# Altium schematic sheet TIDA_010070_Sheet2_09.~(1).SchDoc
size 431 x 279 mm; Date: Not shown in title block; ApprovedBy: Not shown in title block; CheckedBy: Not shown in title block; Author: Not shown in title block; CompanyName: Not shown in title block; Engineer: Not shown in title block; Organization: Not shown in title block; Address1: Not shown in title block; Address2: Not shown in title block; Address3: Not shown in title block; Address4: Not shown in title block; DocumentNumber: 2; Revision: Use project parameter SCH_Rev; SheetNumber: 2; SheetTotal: 3; PageSetup: Record=PageOptions¦CenterHorizontal=True¦CenterVertical=True¦PrintScale=1.00¦XCorrection=1.00¦YCorrection=1.00¦PrintKind=0¦BorderSize=5000000¦LeftOffset=0¦BottomOffset=0¦Orientation=2¦PaperLength=1000¦PaperWidth=1000¦Scale=100¦PaperSource=15¦PrintQuality=600¦MediaType=1¦DitherType=10¦PaperKind=Letter¦PrintScaleMode=1
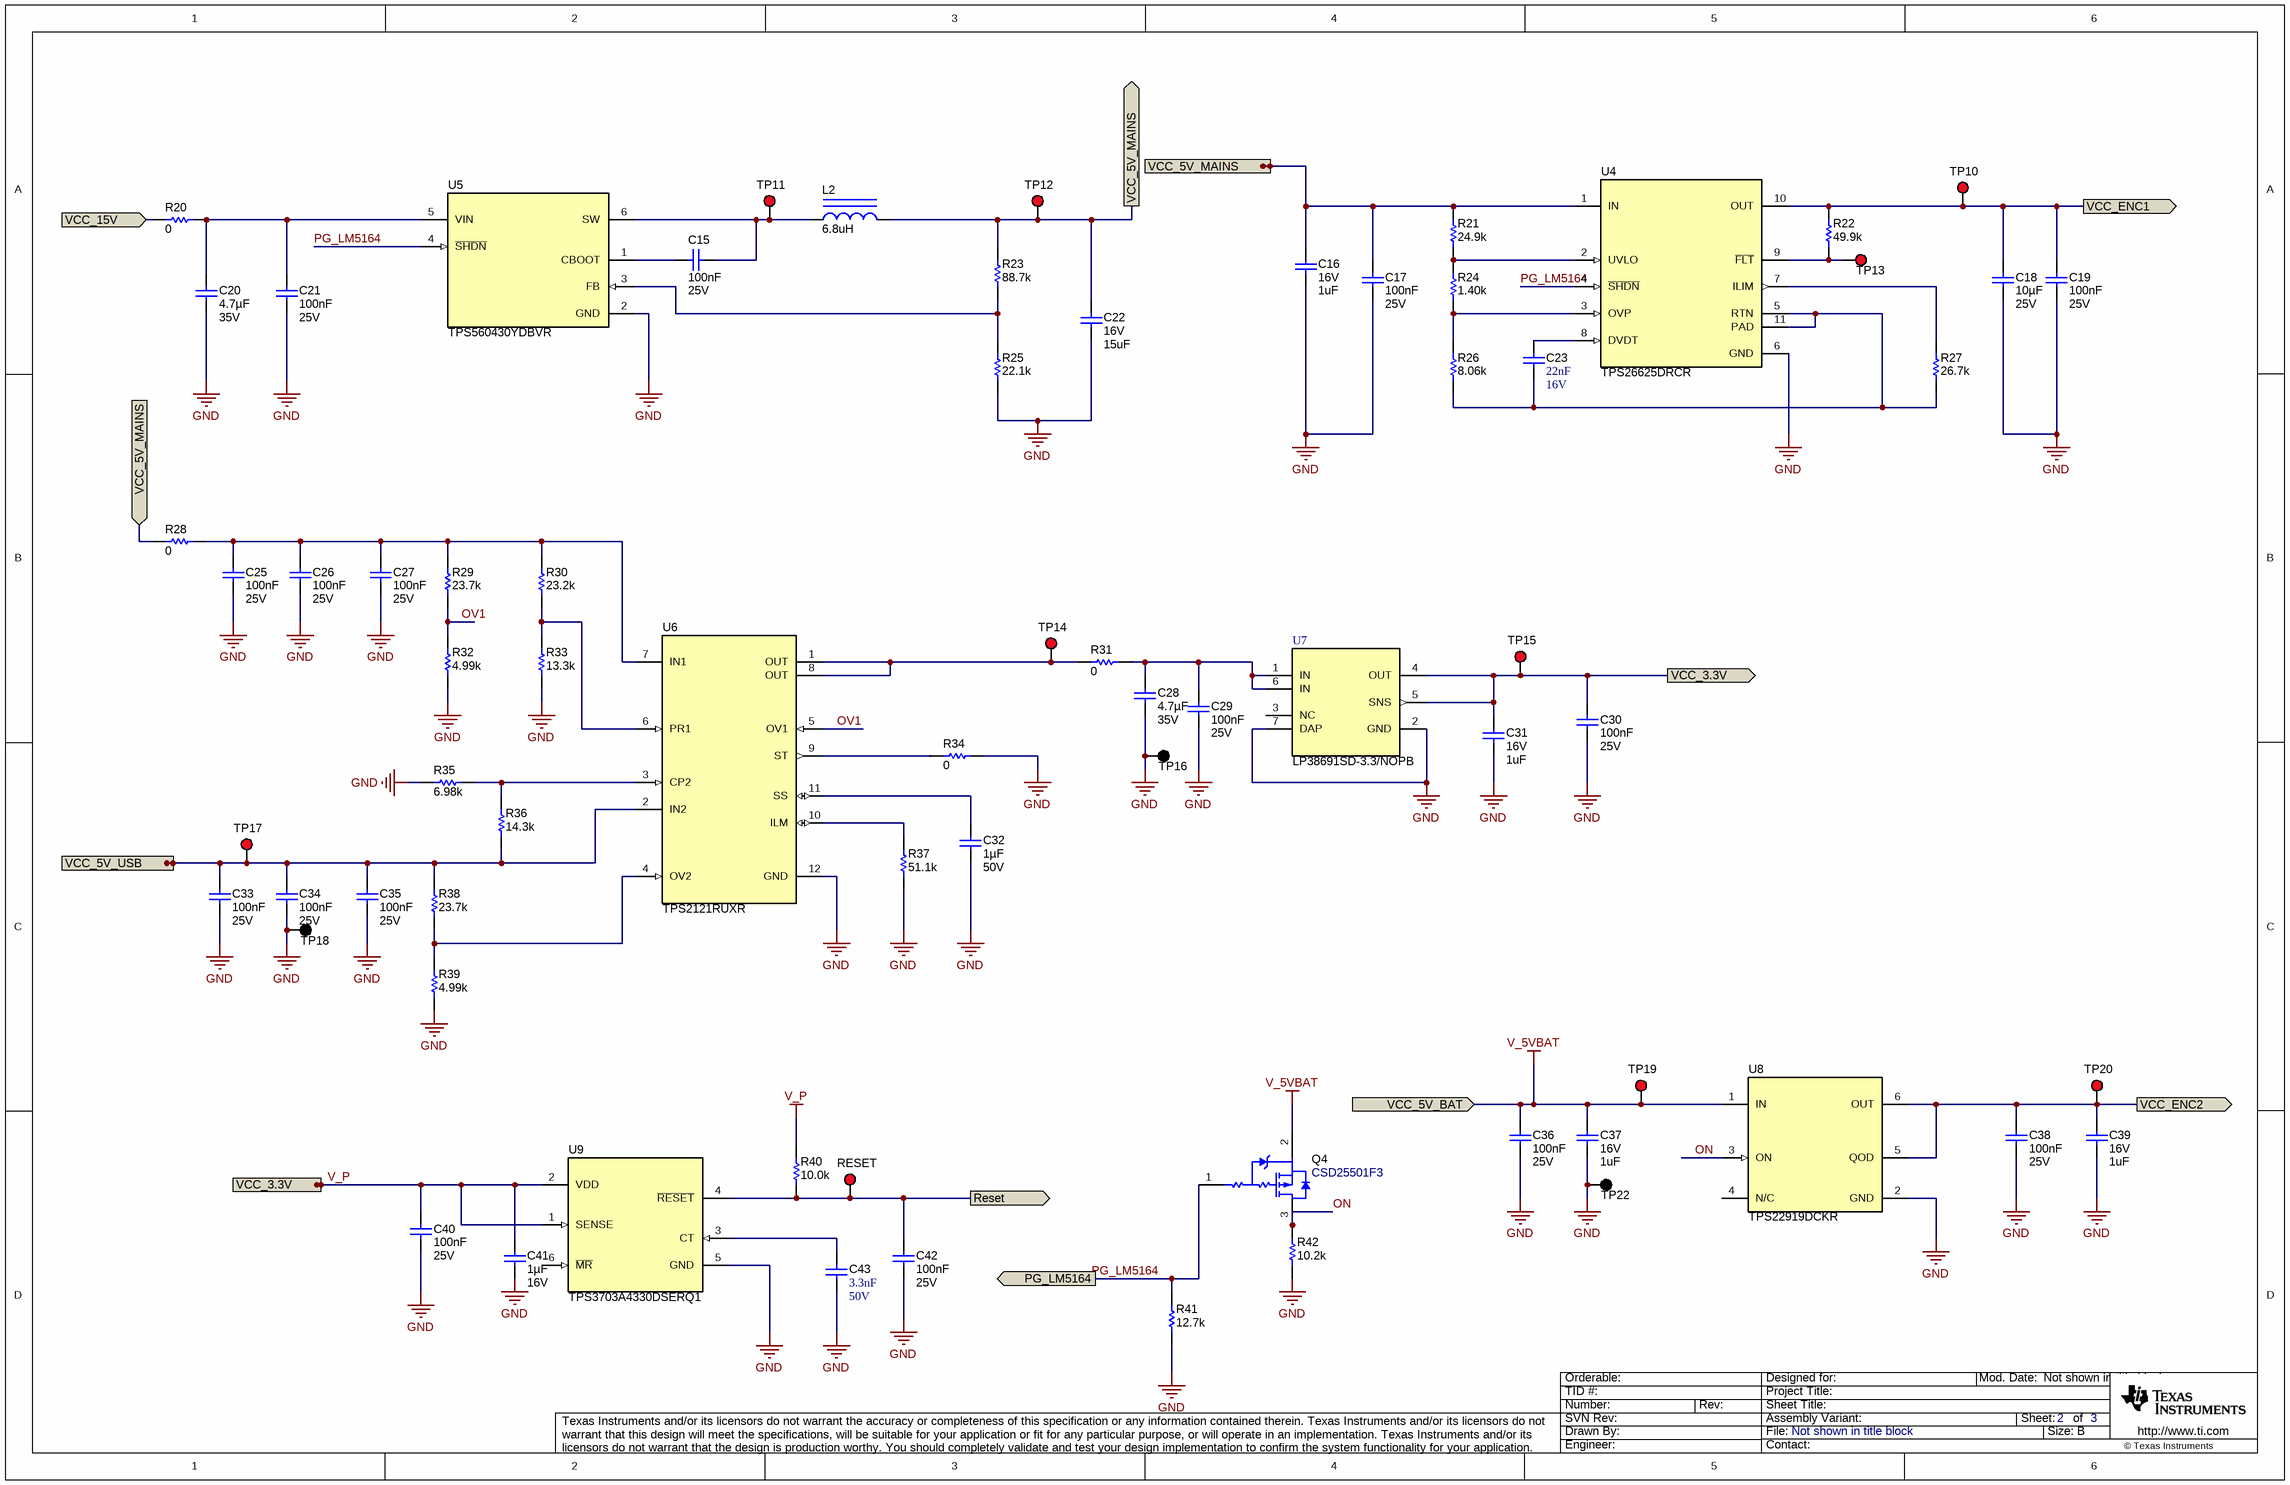
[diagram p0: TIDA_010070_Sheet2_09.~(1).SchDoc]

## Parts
C15  Cap_F: 100nF  VDC_V: 25V  [0603]  (hidden comment: 06033C104KAT2A)
C16  VDC_V: 16V  ValueDisplayed: 1uF  [0805_HV]  (hidden comment: C2012X8R1C105K125AB)
C17  Cap_F: 100nF  VDC_V: 25V  [0603]  (hidden comment: 06033C104KAT2A)
C18  Cap_F: 10µF  VDC_V: 25V  [0805_HV]  (hidden comment: GRM21BZ71E106KE15L)
C19  Cap_F: 100nF  VDC_V: 25V  [0603]  (hidden comment: 06033C104KAT2A)
C20  Cap_F: 4.7µF  VDC_V: 35V  [0805_HV]  (hidden comment: C2012X7R1V475K125AC)
C21  Cap_F: 100nF  VDC_V: 25V  [0603]  (hidden comment: 06033C104KAT2A)
C22  VDC_V: 16V  ValueDisplayed: 15uF  [1210_280]  (hidden comment: C3225X5R1C156M250AA)
C23  Cap_F: 22nF  VDC_V: 16V  [0603]  (hidden comment: C0603C223K4RACTU)
C25  Cap_F: 100nF  VDC_V: 25V  [0603]  (hidden comment: 06033C104KAT2A)
C26  Cap_F: 100nF  VDC_V: 25V  [0603]  (hidden comment: 06033C104KAT2A)
C27  Cap_F: 100nF  VDC_V: 25V  [0603]  (hidden comment: 06033C104KAT2A)
C28  Cap_F: 4.7µF  VDC_V: 35V  [0805_HV]  (hidden comment: C2012X7R1V475K125AC)
C29  Cap_F: 100nF  VDC_V: 25V  [0603]  (hidden comment: 06033C104KAT2A)
C30  Cap_F: 100nF  VDC_V: 25V  [0603]  (hidden comment: 06033C104KAT2A)
C31  VDC_V: 16V  ValueDisplayed: 1uF  [0805_HV]  (hidden comment: C2012X8R1C105K125AB)
C32  Cap_F: 1µF  VDC_V: 50V  [0805_HV]  (hidden comment: C0805C105K5RACTU)
C33  Cap_F: 100nF  VDC_V: 25V  [0603]  (hidden comment: 06033C104KAT2A)
C34  Cap_F: 100nF  VDC_V: 25V  [0603]  (hidden comment: 06033C104KAT2A)
C35  Cap_F: 100nF  VDC_V: 25V  [0603]  (hidden comment: 06033C104KAT2A)
C36  Cap_F: 100nF  VDC_V: 25V  [0603]  (hidden comment: 06033C104KAT2A)
C37  VDC_V: 16V  ValueDisplayed: 1uF  [0805_HV]  (hidden comment: C2012X8R1C105K125AB)
C38  Cap_F: 100nF  VDC_V: 25V  [0603]  (hidden comment: 06033C104KAT2A)
C39  VDC_V: 16V  ValueDisplayed: 1uF  [0805_HV]  (hidden comment: C2012X8R1C105K125AB)
C40  Cap_F: 100nF  VDC_V: 25V  [0603]  (hidden comment: 06033C104KAT2A)
C41  Cap_F: 1µF  VDC_V: 16V  [0603]  (hidden comment: GCM188R71C105KA64D)
C42  Cap_F: 100nF  VDC_V: 25V  [0603]  (hidden comment: 06033C104KAT2A)
C43  Cap_F: 3.3nF  VDC_V: 50V  [0603]  (hidden comment: C0603C332K5RACTU)
L2  ValueDisplayed: 6.8uH  [ME3220]  (hidden comment: ME3220-682MLB)
Q4  CSD25501F3  [YJN0003A]
R20  ValueDisplayed: 0  [5106]  (hidden comment: 5106)
R21  ValueDisplayed: 24.9k  [0603]  (hidden comment: CRCW060324K9FKEA)
R22  ValueDisplayed: 49.9k  [0603]  (hidden comment: CRCW060349K9FKEA)
R23  ValueDisplayed: 88.7k  [0603]  (hidden comment: CRCW060388K7FKEA)
R24  ValueDisplayed: 1.40k  [0603]  (hidden comment: CRCW06031K40FKEA)
R25  ValueDisplayed: 22.1k  [0603]  (hidden comment: CRCW060322K1FKEA)
R26  ValueDisplayed: 8.06k  [0603]  (hidden comment: CRCW06038K06FKEA)
R27  ValueDisplayed: 26.7k  [0603]  (hidden comment: CRCW060326K7FKEA)
R28  ValueDisplayed: 0  [5106]  (hidden comment: 5106)
R29  ValueDisplayed: 23.7k  [0603]  (hidden comment: CRCW060323K7FKEA)
R30  ValueDisplayed: 23.2k  [0603]  (hidden comment: CRCW060323K2FKEA)
R31  ValueDisplayed: 0  [5106]  (hidden comment: 5106)
R32  ValueDisplayed: 4.99k  [0603]  (hidden comment: CRCW06034K99FKEA)
R33  ValueDisplayed: 13.3k  [0603]  (hidden comment: CRCW060313K3FKEA)
R34  ValueDisplayed: 0  [0603]  (hidden comment: CRCW06030000Z0EA)
R35  ValueDisplayed: 6.98k  [0603]  (hidden comment: CRCW06036K98FKEA)
R36  ValueDisplayed: 14.3k  [0603]  (hidden comment: CRCW060314K3FKEA)
R37  ValueDisplayed: 51.1k  [0603]  (hidden comment: CRCW060351K1FKEA)
R38  ValueDisplayed: 23.7k  [0603]  (hidden comment: CRCW060323K7FKEA)
R39  ValueDisplayed: 4.99k  [0603]  (hidden comment: CRCW06034K99FKEA)
R40  ValueDisplayed: 10.0k  [0603]  (hidden comment: CRCW060310K0FKEA)
R41  ValueDisplayed: 12.7k  [0603]  (hidden comment: CRCW060312K7FKEA)
R42  ValueDisplayed: 10.2k  [0603]  (hidden comment: CRCW060310K2FKEA)
RESET  5000  [Keystone5000]  (value not drawn)
TP10  5000  [Keystone5000]  (value not drawn)
TP11  5000  [Keystone5000]  (value not drawn)
TP12  5000  [Keystone5000]  (value not drawn)
TP13  5000  [Keystone5000]  (value not drawn)
TP14  5000  [Keystone5000]  (value not drawn)
TP15  5000  [Keystone5000]  (value not drawn)
TP16  5001  [Keystone5001]  (value not drawn)
TP17  5000  [Keystone5000]  (value not drawn)
TP18  5001  [Keystone5001]  (value not drawn)
TP19  5000  [Keystone5000]  (value not drawn)
TP20  5000  [Keystone5000]  (value not drawn)
TP22  5001  [Keystone5001]  (value not drawn)
U4  TPS26625DRCR  [DRC0010J]
U5  TPS560430YDBVR  [DBV0006A_N]
U6  TPS2121RUXR  [RUX0012A]
U7  LP38691SD-3.3/NOPB  [NGG0006A_V]
U8  TPS22919DCKR  [DCK0006A_N]
U9  TPS3703A4330DSERQ1  [DSE0006A]

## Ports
PG_LM5164 (out), Reset (out), VCC_3.3V (in), VCC_3.3V (out), VCC_5V_BAT (in), VCC_5V_MAINS (in), VCC_5V_MAINS (out), VCC_5V_USB (in), VCC_15V (in), VCC_ENC1 (out), VCC_ENC2 (out)

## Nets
GND: C16.1 C17.2 C18.1 C19.2 C20.1 C21.1 C22.1 C25.1 C26.1 C27.1 C28.1 C29.2 C30.2 C31.1 C32.1 C33.1 C34.1 C35.1 C36.2 C37.1 C38.2 C39.1 C40.2 C41.2 C42.2 C43.2 R25.2 R32.2 R33.2 R34.2 R35.2 R37.2 R39.2 R41.2 R42.2 TP16.1 TP18.1 TP22.1 U4.6(GND) U5.2(GND) U6.12(GND) U7.2(GND) U7.7(DAP) U8.2(GND) U9.5(GND)
V_5VBAT: C36.1 C37.2 Q4.2(S) TP19.1 U8.1(IN) ; port VCC_5V_BAT
V_P: C30.1 C31.2 C40.1 C41.1 R40.2 TP15.1 U7.4(OUT) U7.5(SNS) U9.1(SENSE) U9.2(VDD) ; port VCC_3.3V
ON: Q4.3(D) R42.1 U8.3(ON)
OV1: R29.2 R32.1 U6.5(OV1)
PG_LM5164: U4.4(~{SHDN}) U5.4(~{SHDN})
PG_LM5164: Q4.1(G) R41.1 ; port PG_LM5164  [a separate net that carries the same name]
Reset: C42.1 R40.1 RESET.1 U9.4(~{RESET}) ; port Reset
VCC_5V_MAINS: C16.2 C17.1 C22.2 L2.2 R21.1 R23.1 R28.1 TP12.1 U4.1(IN) ; port VCC_5V_MAINS
VCC_5V_USB: C33.2 C34.2 C35.2 R36.2 R38.1 TP17.1 U6.2(IN2) ; port VCC_5V_USB
VCC_15V: R20.1 ; port VCC_15V
VCC_ENC1: C18.2 C19.1 R22.1 TP10.1 U4.10(OUT) ; port VCC_ENC1
VCC_ENC2: C38.1 C39.2 TP20.1 U8.5(QOD) U8.6(OUT) ; port VCC_ENC2
NetC15_1: C15.1 U5.1(CBOOT)
NetC15_2: C15.2 L2.1 TP11.1 U5.6(SW)
NetC20_2: C20.2 C21.2 R20.2 U5.5(VIN)
NetC23_1: C23.1 U4.8(DVDT)
NetC23_2: C23.2 R26.2 R27.2 U4.5(RTN) U4.11(PAD)
NetC25_2: C25.2 C26.2 C27.2 R28.2 R29.1 R30.1 U6.7(IN1)
NetC28_2: C28.2 C29.1 R31.2 U7.1(IN) U7.6(IN)
NetC32_2: C32.2 U6.11(SS)
NetC43_1: C43.1 U9.3(CT)
NetR21_2: R21.2 R24.1 U4.2(UVLO)
NetR22_2: R22.2 TP13.1 U4.9(~{FLT})
NetR23_2: R23.2 R25.1 U5.3(FB)
NetR24_2: R24.2 R26.1 U4.3(OVP)
NetR27_1: R27.1 U4.7(ILIM)
NetR30_2: R30.2 R33.1 U6.6(PR1)
NetR31_1: R31.1 TP14.1 U6.1(OUT) U6.8(OUT)
NetR34_1: R34.1 U6.9(ST)
NetR35_1: R35.1 R36.1 U6.3(CP2)
NetR37_1: R37.1 U6.10(ILM)
NetR38_2: R38.2 R39.1 U6.4(OV2)

Not connected (* = marked no-connect by the designer): U7 3(NC); U8 4(N/C); U9 6(~{MR})

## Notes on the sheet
- Labels drawn without touching a wire or pin: PG_LM5164

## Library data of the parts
C15 C17 C19 C21 C25-C27 C29 C30 C33-C36 C38 C40 C42 = CMP-0006753-4: CAP, CERM, 0.1 uF, 25 V, +/- 10%, X7R, 0603; Manufacturer: AVX; TaMin_C: -55°C; ESR_ohm: 0.05; Polarized: N; SizeAreaWB_mm2: 4.68; Value1: 0.05 ohm; U/M: EA; Value: 0.1uF; TaMax_C: 125°C; SizeZ_mm: 1; SizeX_mm: 1.6; SizeY_mm: 0.8; SizeArea_mm2: 1.28; AEC Category: Q200
C16 C31 C37 C39 = CMP-0007898-1: CAP, CERM, 1 uF, 16 V, +/- 10%, X8R, 0805; Manufacturer: TDK; TaMin_C: -55°C; Polarized: N; SizeAreaWB_mm2: 6.75; Value1: Unknown; U/M: EA; Value: 1uF; TaMax_C: 150°C; SizeZ_mm: 1.45; SizeX_mm: 2; SizeY_mm: 1.25; Cap_Case: 0805; SizeArea_mm2: 2.5; Cap_F: 1µF; AEC Category: Q200
C18 = CMP-0008378-2: CAP, CERM, 10 uF, 25 V, +/- 10%, X7R, 0805; Manufacturer: MuRata; TaMin_C: -55°C; Polarized: N; SizeAreaWB_mm2: 6.75; Value1: Unknown; U/M: EA; Value: 10uF; TaMax_C: 125°C; SizeZ_mm: 1.45; SizeX_mm: 2; SizeY_mm: 1.25; Cap_Case: 0805; SizeArea_mm2: 2.5; AEC Category: Q200
C20 C28 = CMP-0007885-2: CAP, CERM, 4.7 uF, 35 V, +/- 10%, X7R, 0805; Manufacturer: TDK; TaMin_C: -55°C; ESR_ohm: 2.346m; Polarized: N; SizeAreaWB_mm2: 6.75; Value1: 0.002346 ohm; U/M: EA; Value: 4.7uF; TaMax_C: 125°C; SizeZ_mm: 1.45; SizeX_mm: 2; SizeY_mm: 1.25; Cap_Case: 0805; SizeArea_mm2: 2.5; IRMS_A: 4.26021A; AEC Category: Q200
C22 = CMP-0009102-1: CAP, CERM, 15 uF, 16 V, +/- 20%, X5R, 1210; Manufacturer: TDK; TaMin_C: -55°C; ESR_ohm: 2.949m; Polarized: N; SizeAreaWB_mm2: 14.7; Value1: 0.002949 ohm; U/M: EA; Value: 15uF; TaMax_C: 85°C; SizeZ_mm: 2.8; SizeX_mm: 3.2; SizeY_mm: 2.5; SizeArea_mm2: 8; Cap_F: 15µF; IRMS_A: 4.28133A; AEC Category: Q200
C23 = CMP-0006900-4: CAP, CERM, 0.022 uF, 16 V, +/- 10%, X7R, 0603; Manufacturer: Kemet; TaMin_C: -55°C; Polarized: N; SizeAreaWB_mm2: 4.68; Value1: Unknown; U/M: EA; TaMax_C: 125°C; SizeZ_mm: 1; SizeX_mm: 1.6; SizeY_mm: 0.8; SizeArea_mm2: 1.28; AEC Category: Q200
C32 = CMP-0007730-2: CAP, CERM, 1 uF, 50 V, +/- 10%, X7R, 0805; Manufacturer: Kemet; TaMin_C: -55°C; Polarized: N; SizeAreaWB_mm2: 6.75; Value1: Unknown; U/M: EA; Value: 1uF; TaMax_C: 125°C; SizeZ_mm: 1.45; SizeX_mm: 2; SizeY_mm: 1.25; Cap_Case: 0805; SizeArea_mm2: 2.5; AEC Category: Q200
C41 = CMP-0007136-5: CAP, CERM, 1 uF, 16 V, +/- 10%, X7R, AEC-Q200 Grade 1, 0603; Manufacturer: MuRata; TaMin_C: -55°C; Polarized: N; SizeAreaWB_mm2: 4.68; Value1: Unknown; U/M: EA; Value: 1uF; TaMax_C: 125°C; SizeZ_mm: 1; SizeX_mm: 1.6; SizeY_mm: 0.8; SizeArea_mm2: 1.28; AEC Qualified: Y; AEC Category: Q200
C43 = CMP-0006922-4: CAP, CERM, 3300 pF, 50 V, +/- 10%, X7R, 0603; Manufacturer: Kemet; TaMin_C: -55°C; Polarized: N; SizeAreaWB_mm2: 4.68; Value1: Unknown; U/M: EA; Value: 3300pF; TaMax_C: 125°C; SizeZ_mm: 1; SizeX_mm: 1.6; SizeY_mm: 0.8; SizeArea_mm2: 1.28; AEC Category: Q200
L2 = CMP-0060543-1: Inductor, Drum Core, Ferrite, 6.8 uH, 1.1 A, 0.27 ohm, SMD; Manufacturer: Coilcraft; Isat: 1.2A @ 30% inductance drop; Irms: 1.1A @ 40C rise; Green_Lifecycle: Not Set; SizeAreaWB_mm2: 15.96; DCR_ohm: 0.27; Green_REACh: Incomplete; Value: 6.8uH; Imax_A: 1.1A; SizeZ_mm: 2; SizeX_mm: 3.2; SizeY_mm: 2.8; SizeArea_mm2: 8.96; Ind_H: 6.8µH; AEC Category: Q200
Q4 = CMP-0078322-2: MOSFET, P-CH, -20 V, -3.6 A, YJN0003A (PICOSTAR-3); Manufacturer: Texas Instruments; Alternate Manufacturer: None; SizeArea_mm2: 0.414; VdsMax_V: -20V; QgTyp_nC: 1.02; Value1: 0.076 ohm; AEC Category: Q101; SizeX_mm: 0.69; IdsMax_A: -3.6A; Value: -20V; Rdson45_ohm: 0.076; Value2: 1.02 nC; SizeAreaWB_mm2: 2.704; SizeZ_mm: 0.22; SizeY_mm: 0.6; ChType: P; AEC Qualified: N; ChMode: Enhancement
R20 R28 R31 = CMP-0020833-2: RES, 0, 1%, 0.5 W, 0805; Manufacturer: Keystone; Power_W: 500mW; TempCo: ppm/C; U/M: EA; Value: 0; SizeX_mm: 2; SizeY_mm: 1.25; SizeZ_mm: 0.84; Value2: 0.5W; SizeArea_mm2: 2.5; AEC Qualified: N; AEC Category: Q200
R21 = CMP-0022237-4: RES, 24.9 k, 1%, 0.1 W, AEC-Q200 Grade 0, 0603; Manufacturer: Vishay-Dale; Power_W: 100mW; TempCo: 100 ppm/C; Value_Code: 24k9; Value: 24.9k; EIA_Code: E96; SizeX_mm: 1.6; SizeY_mm: 0.8; SizeZ_mm: 1; Value2: 0.1W; SizeArea_mm2: 1.28; AEC Qualified: Y; VDC_V: 75V; AEC Category: Q200; AEC Grade: 0
R22 = CMP-0022447-4: RES, 49.9 k, 1%, 0.1 W, AEC-Q200 Grade 0, 0603; Manufacturer: Vishay-Dale; Power_W: 100mW; TempCo: 100 ppm/C; Value_Code: 49k9; Value: 49.9k; EIA_Code: E96; SizeX_mm: 1.6; SizeY_mm: 0.8; SizeZ_mm: 1; Value2: 0.1W; SizeArea_mm2: 1.28; AEC Qualified: Y; VDC_V: 75V; AEC Category: Q200; AEC Grade: 0
R23 = CMP-0022632-4: RES, 88.7 k, 1%, 0.1 W, AEC-Q200 Grade 0, 0603; Manufacturer: Vishay-Dale; Power_W: 100mW; TempCo: 100 ppm/C; Value_Code: 88k7; Value: 88.7k; EIA_Code: E96; SizeX_mm: 1.6; SizeY_mm: 0.8; SizeZ_mm: 1; Value2: 0.1W; SizeArea_mm2: 1.28; AEC Qualified: Y; VDC_V: 75V; AEC Category: Q200; AEC Grade: 0
R24 = CMP-0022123-4: RES, 1.40 k, 1%, 0.1 W, AEC-Q200 Grade 0, 0603; Manufacturer: Vishay-Dale; Power_W: 100mW; TempCo: 100 ppm/C; Value_Code: 1k40; Value: 1.40k; EIA_Code: E96; Res_ohm: 1.4k; SizeX_mm: 1.6; SizeY_mm: 0.8; SizeZ_mm: 1; Value2: 0.1W; SizeArea_mm2: 1.28; AEC Qualified: Y; VDC_V: 75V; AEC Category: Q200; AEC Grade: 0
R25 = CMP-0022220-4: RES, 22.1 k, 1%, 0.1 W, AEC-Q200 Grade 0, 0603; Manufacturer: Vishay-Dale; Power_W: 100mW; TempCo: 100 ppm/C; Value_Code: 22k1; Value: 22.1k; EIA_Code: E96; SizeX_mm: 1.6; SizeY_mm: 0.8; SizeZ_mm: 1; Value2: 0.1W; SizeArea_mm2: 1.28; AEC Qualified: Y; VDC_V: 75V; AEC Category: Q200; AEC Grade: 0
R26 = CMP-0022634-4: RES, 8.06 k, 1%, 0.1 W, AEC-Q200 Grade 0, 0603; Manufacturer: Vishay-Dale; Power_W: 100mW; TempCo: 100 ppm/C; Value_Code: 8k06; Value: 8.06k; EIA_Code: E96; SizeX_mm: 1.6; SizeY_mm: 0.8; SizeZ_mm: 1; Value2: 0.1W; SizeArea_mm2: 1.28; AEC Qualified: Y; VDC_V: 75V; AEC Category: Q200; AEC Grade: 0
R27 = CMP-0022249-4: RES, 26.7 k, 1%, 0.1 W, AEC-Q200 Grade 0, 0603; Manufacturer: Vishay-Dale; Power_W: 100mW; TempCo: 100 ppm/C; Value_Code: 26k7; Value: 26.7k; EIA_Code: E96; SizeX_mm: 1.6; SizeY_mm: 0.8; SizeZ_mm: 1; Value2: 0.1W; SizeArea_mm2: 1.28; AEC Qualified: Y; VDC_V: 75V; AEC Category: Q200; AEC Grade: 0
R29 R38 = CMP-0022229-4: RES, 23.7 k, 1%, 0.1 W, AEC-Q200 Grade 0, 0603; Manufacturer: Vishay-Dale; Power_W: 100mW; TempCo: 100 ppm/C; Value_Code: 23k7; Value: 23.7k; EIA_Code: E96; SizeX_mm: 1.6; SizeY_mm: 0.8; SizeZ_mm: 1; Value2: 0.1W; SizeArea_mm2: 1.28; AEC Qualified: Y; VDC_V: 75V; AEC Category: Q200; AEC Grade: 0
R30 = CMP-0022228-4: RES, 23.2 k, 1%, 0.1 W, AEC-Q200 Grade 0, 0603; Manufacturer: Vishay-Dale; Power_W: 100mW; TempCo: 100 ppm/C; Value_Code: 23k2; Value: 23.2k; EIA_Code: E96; SizeX_mm: 1.6; SizeY_mm: 0.8; SizeZ_mm: 1; Value2: 0.1W; SizeArea_mm2: 1.28; AEC Qualified: Y; VDC_V: 75V; AEC Category: Q200; AEC Grade: 0
R32 R39 = CMP-0022458-4: RES, 4.99 k, 1%, 0.1 W, AEC-Q200 Grade 0, 0603; Manufacturer: Vishay-Dale; Power_W: 100mW; TempCo: 100 ppm/C; Value_Code: 4k99; Value: 4.99k; EIA_Code: E96; SizeX_mm: 1.6; SizeY_mm: 0.8; SizeZ_mm: 1; Value2: 0.1W; SizeArea_mm2: 1.28; AEC Qualified: Y; VDC_V: 75V; AEC Category: Q200; AEC Grade: 0
R33 = CMP-0022043-4: RES, 13.3 k, 1%, 0.1 W, AEC-Q200 Grade 0, 0603; Manufacturer: Vishay-Dale; Power_W: 100mW; TempCo: 100 ppm/C; Value_Code: 13k3; Value: 13.3k; EIA_Code: E96; SizeX_mm: 1.6; SizeY_mm: 0.8; SizeZ_mm: 1; Value2: 0.1W; SizeArea_mm2: 1.28; AEC Qualified: Y; VDC_V: 75V; AEC Category: Q200; AEC Grade: 0
R34 = CMP-0025697-4: RES, 0, 5%, 0.1 W, AEC-Q200 Grade 0, 0603; Manufacturer: Vishay-Dale; Power_W: 100mW; TempCo: 200 ppm/C; Value_Code: 0000; Value: 0; EIA_Code: E24; SizeX_mm: 1.6; SizeY_mm: 0.8; SizeZ_mm: 1; Value2: 0.1W; SizeArea_mm2: 1.28; AEC Qualified: Y; VDC_V: 75V; AEC Category: Q200
R35 = CMP-0022564-4: RES, 6.98 k, 1%, 0.1 W, AEC-Q200 Grade 0, 0603; Manufacturer: Vishay-Dale; Power_W: 100mW; TempCo: 100 ppm/C; Value_Code: 6k98; Value: 6.98k; EIA_Code: E96; SizeX_mm: 1.6; SizeY_mm: 0.8; SizeZ_mm: 1; Value2: 0.1W; SizeArea_mm2: 1.28; AEC Qualified: Y; VDC_V: 75V; AEC Category: Q200; AEC Grade: 0
R36 = CMP-0022055-4: RES, 14.3 k, 1%, 0.1 W, AEC-Q200 Grade 0, 0603; Manufacturer: Vishay-Dale; Power_W: 100mW; TempCo: 100 ppm/C; Value_Code: 14k3; Value: 14.3k; EIA_Code: E96; SizeX_mm: 1.6; SizeY_mm: 0.8; SizeZ_mm: 1; Value2: 0.1W; SizeArea_mm2: 1.28; AEC Qualified: Y; VDC_V: 75V; AEC Category: Q200; AEC Grade: 0
R37 = CMP-0022482-4: RES, 51.1 k, 1%, 0.1 W, AEC-Q200 Grade 0, 0603; Manufacturer: Vishay-Dale; Power_W: 100mW; TempCo: 100 ppm/C; Value_Code: 51k1; Value: 51.1k; EIA_Code: E96; SizeX_mm: 1.6; SizeY_mm: 0.8; SizeZ_mm: 1; Value2: 0.1W; SizeArea_mm2: 1.28; AEC Qualified: Y; VDC_V: 75V; AEC Category: Q200; AEC Grade: 0
R40 = CMP-0021998-4: RES, 10.0 k, 1%, 0.1 W, AEC-Q200 Grade 0, 0603; Manufacturer: Vishay-Dale; Power_W: 100mW; TempCo: 100 ppm/C; Value_Code: 10k0; Value: 10.0k; EIA_Code: E96; Res_ohm: 10k; SizeX_mm: 1.6; SizeY_mm: 0.8; SizeZ_mm: 1; Value2: 0.1W; SizeArea_mm2: 1.28; AEC Qualified: Y; VDC_V: 75V; AEC Category: Q200; AEC Grade: 0
R41 = CMP-0022032-4: RES, 12.7 k, 1%, 0.1 W, AEC-Q200 Grade 0, 0603; Manufacturer: Vishay-Dale; Power_W: 100mW; TempCo: 100 ppm/C; Value_Code: 12k7; Value: 12.7k; EIA_Code: E96; SizeX_mm: 1.6; SizeY_mm: 0.8; SizeZ_mm: 1; Value2: 0.1W; SizeArea_mm2: 1.28; AEC Qualified: Y; VDC_V: 75V; AEC Category: Q200; AEC Grade: 0
R42 = CMP-0021999-4: RES, 10.2 k, 1%, 0.1 W, AEC-Q200 Grade 0, 0603; Manufacturer: Vishay-Dale; Power_W: 100mW; TempCo: 100 ppm/C; Value_Code: 10k2; Value: 10.2k; EIA_Code: E96; SizeX_mm: 1.6; SizeY_mm: 0.8; SizeZ_mm: 1; Value2: 0.1W; SizeArea_mm2: 1.28; AEC Qualified: Y; VDC_V: 75V; AEC Category: Q200; AEC Grade: 0
RESET TP10-TP15 TP17 TP19 TP20 = CMP-0055137-1: Test Point, Miniature, Red, TH; Manufacturer: Keystone; CNHeader: FALSE; Green_Lifecycle: Active; Green_REACh: Passed; ContactFinish: Silver; CT: TRUE
TP16 TP18 TP22 = CMP-0055138-1: Test Point, Miniature, Black, TH; Manufacturer: Keystone; CNHeader: FALSE; Green_Lifecycle: Active; Green_REACh: Passed; ContactFinish: Silver; CT: TRUE
U4 = CMP-0013395-7: 60-V, 800-mA Industrial eFuse with Integrated Reverse Polarity Protection, DRC0010J (VSON-10); Manufacturer: Texas Instruments; Alternate PartNumber: TPS26625DRCT; SizeY_mm: 3; CompType: IC; SizeAreaWB_mm2: 16; AEC Qualified: N; Rating: Catalog; SizeZ_mm: 1; SizeArea_mm2: 9; AEC Category: Q200
U5 = CMP-0065101-2: 4V to 36 V 0.6 A Synchronous Step-Down Converter, DBV0006A (SOT-23-6); Manufacturer: Texas Instruments; Alternate PartNumber: TPS560430YDBVT; SizeX_mm: 2.8; SizeY_mm: 2.9; CompType: IC; SizeZ_mm: 1.45; SizeArea_mm2: 8.12; SizeAreaWB_mm2: 14.82; U/M: EA
U6 = CMP-0078351-3: 2.7V-22V, 4A, 50mohm Priority Power MUX, RUX0012A (VQFN-HR-12); Alternate PartNumber: TPS2121RUXT; Alternate Manufacturer: Texas Instruments; SizeAreaWB_mm2: 10.5; SizeZ_mm: 1; SizeX_mm: 2; SizeY_mm: 2.5; SizeArea_mm2: 5; CompType: IC; AEC Qualified: N; AEC Category: Q200
U7 = CMP-0070735-1: 500mA Low Dropout CMOS Linear Regulators Stable with Ceramic Output Capacitors, 6-pin LLP, Pb-Free, 1000 Reel; Manufacturer: Texas Instruments; CompType: LDO IC; PackageTopMarking: ZXYTT*L120B; High-Reliability: Y
U8 = CMP-0081108-1: 5.5-V, 1.5-A, 100-mohm Load Switch with Output Discharge, DCK0006A (SOT-SC70-6); Alternate PartNumber: TPS22919DCKT; Alternate Manufacturer: Texas Instruments; SizeAreaWB_mm2: 9.3; SizeZ_mm: 1.1; SizeX_mm: 2.1; SizeY_mm: 2; SizeArea_mm2: 4.2; CompType: IC; AEC Qualified: N; AEC Category: Q200
U9 = CMP-0750051-1: Overvoltage and Undervoltage Reset IC With Time Delay and Manual Reset, DSE0006A (WSON-6); Alternate Manufacturer: Texas Instruments; AEC Category: Q200; SizeY_mm: 1.5; AEC Qualified: Y; SizeAreaWB_mm2: 6.25; SizeZ_mm: 0.8; SizeArea_mm2: 2.25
